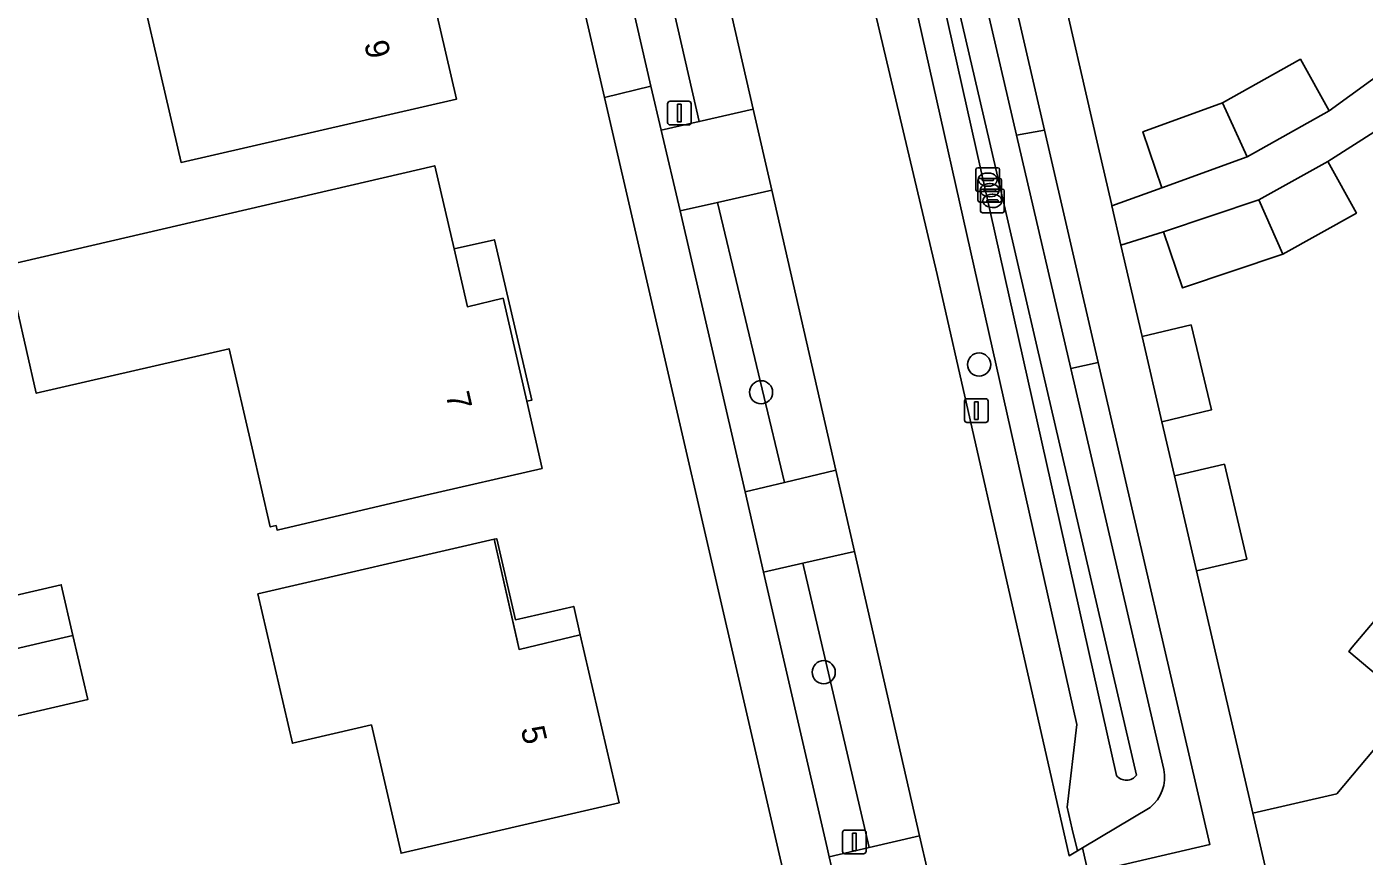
# Model space of a CAD drawing. Extents: x 156412 to 157779, y 382335 to 383768.
# Drawn here: x 156724.8 to 156781.3, y 382497.6 to 382532.6 of the extents above; entities that cross this region are included whole.
import ezdxf

# ---------------------------------------------------------------- set-up
doc = ezdxf.new("R2010")
doc.units = 0
for name, color, linetype in [('IMGEO_Berm_groen', 7, 'Continuous'), ('IMGEO_Boom', 7, 'Continuous'), ('IMGEO_Erf', 7, 'Continuous'), ('IMGEO_Greppel_droge_sloot', 7, 'Continuous'), ('IMGEO_Groenvoorziening', 7, 'Continuous'), ('IMGEO_Haag', 7, 'Continuous'), ('IMGEO_Kolk', 7, 'Continuous'), ('IMGEO_Lichtmast', 7, 'Continuous'), ('IMGEO_Muur', 7, 'Continuous'), ('IMGEO_Oever', 7, 'Continuous'), ('IMGEO_Pand', 7, 'Continuous'), ('IMGEO_Pand_nummerreeks', 7, 'Continuous'), ('IMGEO_Pand_overbouw', 7, 'Continuous'), ('IMGEO_Parkeervlak_halfverhard', 7, 'Continuous'), ('IMGEO_Rijbaan_lokaal_gesloten', 7, 'Continuous'), ('IMGEO_Rijbaan_lokaal_open', 7, 'Continuous'), ('IMGEO_Voetpad_open', 7, 'Continuous')]:
    doc.layers.add(name, color=color, linetype=linetype)

msp = doc.modelspace()

# ---------------------------------------------------------------- linework, layer by layer
at = {"layer": 'IMGEO_Berm_groen'}
for points in [[(156761.17, 382551.497), (156766.618, 382528.052), (156767.799, 382528.265), (156761.759, 382554.359), (156755.942, 382553.09), (156763.253, 382522.164), (156768.84, 382497.586), (156769.196, 382497.794), (156768.975, 382498.713), (156768.76, 382499.635), (156769.162, 382503.135), (156758.444, 382550.927)], [(156770.072, 382518.443), (156768.911, 382518.185), (156772.85, 382501.232)], [(156772.262, 382499.622), (156769.404, 382497.915), (156769.645, 382496.868), (156774.79, 382498.059), (156770.072, 382518.443)]]:
    msp.add_lwpolyline(points, dxfattribs=at)
for points in [[(156750.596, 382539.967), (156748.98, 382539.595), (156751.144, 382530.124), (156751.594, 382528.262), (156753.199, 382528.63)], [(156753.975, 382525.21), (156752.389, 382524.85), (156755.144, 382512.971), (156756.797, 382513.365)], [(156757.579, 382509.955), (156755.922, 382509.575), (156758.61, 382497.915), (156758.696, 382497.546), (156760.378, 382497.938)]]:
    msp.add_lwpolyline(points, close=True, dxfattribs=at)
msp.add_arc((156771.214, 382500.917), 1.666, 308.9884, 10.8855, dxfattribs=at)
at = {"layer": 'IMGEO_Boom'}
for centre in [(156765.034, 382518.358), (156755.813, 382517.184), (156758.461, 382505.347)]:
    msp.add_circle(centre, 0.489, dxfattribs=at)
at = {"layer": 'IMGEO_Erf'}
for points in [[(156752.438, 382451.193), (156764.119, 382465.046), (156760.304, 382481.722), (156756.624, 382497.478), (156749.185, 382529.649), (156731.446, 382606.382), (156727.839, 382622.057), (156720.348, 382620.401), (156721.249, 382616.488), (156722.772, 382616.838), (156724.915, 382607.561), (156715.64, 382605.418), (156713.892, 382612.982), (156707.186, 382611.397), (156705.872, 382617.015), (156705.651, 382617.283), (156696.258, 382615.091), (156722.867, 382500), (156729.689, 382470.495)], [(156734.136, 382540.407), (156736.368, 382540.926), (156737.306, 382536.85), (156739.393, 382537.323), (156740.204, 382537.506), (156740.776, 382535.058), (156741.624, 382535.247), (156742.933, 382529.583), (156731.282, 382526.906), (156729.618, 382534.069), (156729.416, 382534.937), (156725.893, 382534.106), (156725.018, 382537.78), (156724.904, 382538.26)], [(156742.013, 382526.766), (156742.829, 382523.243), (156743.395, 382520.802), (156744.902, 382521.157), (156745.9, 382516.805), (156746.552, 382513.962), (156741.638, 382512.837), (156735.345, 382511.36), (156735.3, 382511.551), (156735.054, 382511.494), (156734.286, 382514.824), (156733.315, 382519.028), (156725.158, 382517.143), (156723.923, 382522.561)], [(156744.52, 382510.968), (156745.581, 382506.311), (156748.168, 382506.925), (156749.808, 382499.824), (156740.589, 382497.695), (156739.336, 382503.119), (156735.991, 382502.347), (156734.532, 382508.661)], [(156727.346, 382504.197), (156723.761, 382503.366), (156723.129, 382506.072), (156721.653, 382505.729), (156721.156, 382507.872), (156726.217, 382509.046), (156726.714, 382506.903)]]:
    msp.add_lwpolyline(points, close=True, dxfattribs=at)
for points in [[(156782.269, 382547.821), (156776.998, 382546.602), (156771.884, 382545.42), (156772.162, 382544.211), (156772.024, 382544.18), (156766.55, 382542.92), (156770.067, 382527.583), (156770.629, 382525.152), (156770.648, 382525.072), (156772.758, 382525.835), (156771.958, 382528.204), (156775.328, 382529.423), (156778.62, 382531.268), (156779.843, 382529.087), (156783.336, 382531.627)], [(156782.854, 382528.897), (156779.774, 382526.948), (156780.99, 382524.764), (156777.878, 382523.03), (156773.637, 382521.596), (156772.836, 382523.964), (156771.034, 382523.398), (156771.928, 382519.54), (156773.999, 382520.034), (156774.857, 382516.441), (156772.762, 382515.941), (156773.291, 382513.654), (156775.406, 382514.141), (156776.362, 382510.131), (156774.221, 382509.638), (156776.61, 382499.385), (156780.161, 382500.209), (156783.34, 382503.976), (156780.665, 382506.23), (156780.814, 382506.406), (156784.311, 382510.531)]]:
    msp.add_lwpolyline(points, dxfattribs=at)
at = {"layer": 'IMGEO_Greppel_droge_sloot'}
for points in [[(156759.578, 382551.27), (156770.846, 382500.975)], [(156765.467, 382527.785), (156760.034, 382551.167)], [(156771.692, 382500.993), (156767.76, 382517.918), (156765.467, 382527.785)]]:
    msp.add_lwpolyline(points, dxfattribs=at)
msp.add_arc((156771.262, 382501.322), 0.542, 219.8792, 322.5585, dxfattribs=at)
at = {"layer": 'IMGEO_Groenvoorziening'}
msp.add_lwpolyline([(156767.799, 382528.265), (156766.618, 382528.052), (156768.911, 382518.185), (156770.072, 382518.443)], close=True, dxfattribs=at)
at = {"layer": 'IMGEO_Haag'}
msp.add_lwpolyline([(156767.799, 382528.265), (156766.618, 382528.052), (156768.911, 382518.185), (156770.072, 382518.443)], close=True, dxfattribs=at)
at = {"layer": 'IMGEO_Kolk'}
for p, q in [((156764.899, 382525.75), (156764.899, 382526.602)), ((156764.974, 382526.676), (156765.826, 382526.676)), ((156765.9, 382526.602), (156765.9, 382525.75)), ((156764.983, 382525.301), (156764.983, 382526.153)), ((156765.058, 382526.227), (156765.91, 382526.227)), ((156765.158, 382526.17), (156765.158, 382526.182)), ((156765.596, 382526.133), (156765.198, 382526.133)), ((156765.201, 382526.219), (156765.599, 382526.219)), ((156765.387, 382526.456), (156765.412, 382526.456)), ((156765.471, 382526.007), (156765.496, 382526.007)), ((156765.642, 382526.182), (156765.642, 382526.17)), ((156765.984, 382526.153), (156765.984, 382525.301)), ((156765.826, 382525.676), (156764.974, 382525.676)), ((156765.097, 382524.849), (156765.097, 382525.701)), ((156765.172, 382525.775), (156766.024, 382525.775)), ((156765.242, 382525.721), (156765.242, 382525.733)), ((156765.68, 382525.684), (156765.282, 382525.684)), ((156765.285, 382525.77), (156765.683, 382525.77)), ((156765.41, 382525.896), (156765.385, 382525.896)), ((156765.494, 382525.447), (156765.469, 382525.447)), ((156765.585, 382525.555), (156765.61, 382525.555)), ((156765.726, 382525.733), (156765.726, 382525.721)), ((156766.098, 382525.701), (156766.098, 382524.849)), ((156765.91, 382525.227), (156765.058, 382525.227)), ((156765.356, 382525.269), (156765.356, 382525.281)), ((156765.794, 382525.232), (156765.396, 382525.232)), ((156765.399, 382525.318), (156765.797, 382525.318)), ((156765.608, 382524.995), (156765.583, 382524.995)), ((156765.84, 382525.281), (156765.84, 382525.269)), ((156766.024, 382524.775), (156765.172, 382524.775))]:
    msp.add_line(p, q, dxfattribs=at)
for points in [[(156764.899, 382525.75), (156764.899, 382526.602)], [(156764.974, 382526.676), (156765.826, 382526.676)], [(156765.9, 382526.602), (156765.9, 382525.75)], [(156764.983, 382525.301), (156764.983, 382526.153)], [(156765.058, 382526.227), (156765.91, 382526.227)], [(156765.984, 382526.153), (156765.984, 382525.301)], [(156765.826, 382525.676), (156764.974, 382525.676)], [(156765.097, 382524.849), (156765.097, 382525.701)], [(156765.172, 382525.775), (156766.024, 382525.775)], [(156766.098, 382525.701), (156766.098, 382524.849)], [(156765.91, 382525.227), (156765.058, 382525.227)], [(156766.024, 382524.775), (156765.172, 382524.775)]]:
    msp.add_lwpolyline(points, dxfattribs=at)
for centre, radius, start, end in [((156764.976, 382526.6), 0.0765, 91.552, 178.448), ((156764.976, 382526.6), 0.0765, 91.552, 178.448), ((156765.824, 382526.6), 0.0765, 1.552, 88.448), ((156765.824, 382526.6), 0.0765, 1.552, 88.448), ((156765.06, 382526.151), 0.0765, 91.552, 178.448), ((156765.06, 382526.151), 0.0765, 91.552, 178.448), ((156765.198, 382526.179), 0.0403, 85.8775, 175.7526), ((156765.195, 382526.169), 0.0366, 178.938, 274.7102), ((156765.599, 382526.176), 0.043, 264.8664, 352.4533), ((156765.603, 382526.181), 0.0386, 1.7309, 96.639), ((156765.908, 382526.151), 0.0765, 1.552, 88.448), ((156765.908, 382526.151), 0.0765, 1.552, 88.448), ((156764.976, 382525.752), 0.0765, 181.552, 268.448), ((156764.976, 382525.752), 0.0765, 181.552, 268.448), ((156765.174, 382525.699), 0.0765, 91.552, 178.448), ((156765.174, 382525.699), 0.0765, 91.552, 178.448), ((156765.282, 382525.73), 0.0403, 85.8775, 175.7526), ((156765.279, 382525.72), 0.0366, 178.938, 274.7102), ((156765.683, 382525.727), 0.043, 264.8664, 352.4533), ((156765.687, 382525.732), 0.0386, 1.7309, 96.639), ((156765.824, 382525.752), 0.0765, 271.552, 358.448), ((156765.824, 382525.752), 0.0765, 271.552, 358.448), ((156766.022, 382525.699), 0.0765, 1.552, 88.448), ((156766.022, 382525.699), 0.0765, 1.552, 88.448), ((156765.06, 382525.303), 0.0765, 181.552, 268.448), ((156765.06, 382525.303), 0.0765, 181.552, 268.448), ((156765.174, 382524.851), 0.0765, 181.552, 268.448), ((156765.174, 382524.851), 0.0765, 181.552, 268.448), ((156765.396, 382525.278), 0.0403, 85.8775, 175.7526), ((156765.393, 382525.268), 0.0366, 178.938, 274.7102), ((156765.797, 382525.275), 0.043, 264.8664, 352.4533), ((156765.801, 382525.28), 0.0386, 1.7309, 96.639), ((156765.908, 382525.303), 0.0765, 271.552, 358.448), ((156765.908, 382525.303), 0.0765, 271.552, 358.448), ((156766.022, 382524.851), 0.0765, 271.552, 358.448), ((156766.022, 382524.851), 0.0765, 271.552, 358.448)]:
    msp.add_arc(centre, radius, start, end, dxfattribs=at)
for centre, major_axis, ratio, start_param, end_param in [((156765.386, 382526.176), (-0.387, 0.002), 0.722429, 4.712389, 7.853982), ((156765.47, 382525.727), (-0.387, 0.002), 0.722429, 4.712389, 7.853982), ((156765.411, 382526.176), (-0.39, 0.002), 0.717154, 1.570796, 4.712389), ((156765.495, 382525.727), (-0.39, 0.002), 0.717154, 1.570796, 4.712389), ((156765.584, 382525.275), (-0.387, 0.002), 0.722429, 4.712389, 7.853982), ((156765.609, 382525.275), (-0.39, 0.002), 0.717154, 1.570796, 4.712389)]:
    msp.add_ellipse(centre, major_axis=major_axis, ratio=ratio, start_param=start_param, end_param=end_param, dxfattribs=at)
at = {"layer": 'IMGEO_Lichtmast'}
for p, q in [((156751.862, 382528.588), (156751.862, 382529.388)), ((156751.862, 382529.388), (156751.862, 382528.588)), ((156751.962, 382529.488), (156752.752, 382529.488)), ((156752.752, 382529.488), (156751.962, 382529.488)), ((156752.852, 382529.388), (156752.852, 382528.588)), ((156752.852, 382528.588), (156752.852, 382529.388)), ((156752.752, 382528.488), (156751.962, 382528.488)), ((156751.962, 382528.488), (156752.752, 382528.488)), ((156764.521, 382516.912), (156765.311, 382516.912)), ((156765.311, 382516.912), (156764.521, 382516.912)), ((156764.421, 382516.012), (156764.421, 382516.812)), ((156764.421, 382516.812), (156764.421, 382516.012)), ((156765.411, 382516.812), (156765.411, 382516.012)), ((156765.411, 382516.012), (156765.411, 382516.812)), ((156765.311, 382515.912), (156764.521, 382515.912)), ((156764.521, 382515.912), (156765.311, 382515.912)), ((156759.261, 382497.771), (156759.261, 382498.571)), ((156759.261, 382498.571), (156759.261, 382497.771)), ((156759.361, 382498.671), (156760.151, 382498.671)), ((156760.151, 382498.671), (156759.361, 382498.671)), ((156760.251, 382498.571), (156760.251, 382497.771)), ((156760.251, 382497.771), (156760.251, 382498.571)), ((156760.151, 382497.671), (156759.361, 382497.671)), ((156759.361, 382497.671), (156760.151, 382497.671))]:
    msp.add_line(p, q, dxfattribs=at)
for points in [[(156752.282, 382529.363), (156752.432, 382529.363), (156752.432, 382528.613), (156752.282, 382528.613), (156752.282, 382529.363)], [(156764.841, 382516.787), (156764.991, 382516.787), (156764.991, 382516.037), (156764.841, 382516.037), (156764.841, 382516.787)], [(156759.681, 382498.546), (156759.831, 382498.546), (156759.831, 382497.796), (156759.681, 382497.796), (156759.681, 382498.546)]]:
    msp.add_lwpolyline(points, dxfattribs=at)
for centre, start, end in [((156751.962, 382529.388), 90, 180), ((156751.962, 382529.388), 90, 180), ((156752.752, 382529.388), 0, 90), ((156752.752, 382529.388), 360, 90), ((156751.962, 382528.588), 180, 270), ((156751.962, 382528.588), 180, 270), ((156752.752, 382528.588), 270, 0), ((156752.752, 382528.588), 270, 0), ((156764.521, 382516.812), 90, 180), ((156764.521, 382516.812), 90, 180), ((156765.311, 382516.812), 0, 90), ((156765.311, 382516.812), 360, 90), ((156764.521, 382516.012), 180, 270), ((156764.521, 382516.012), 180, 270), ((156765.311, 382516.012), 270, 0), ((156765.311, 382516.012), 270, 0), ((156759.361, 382498.571), 90, 180), ((156759.361, 382498.571), 90, 180), ((156760.151, 382498.571), 0, 90), ((156760.151, 382498.571), 360, 90), ((156759.361, 382497.771), 180, 270), ((156759.361, 382497.771), 180, 270), ((156760.151, 382497.771), 270, 0), ((156760.151, 382497.771), 270, 0)]:
    msp.add_arc(centre, 0.1, start, end, dxfattribs=at)
at = {"layer": 'IMGEO_Muur'}
for points in [[(156770.067, 382527.583), (156766.55, 382542.92)], [(156770.629, 382525.152), (156770.067, 382527.583)], [(156776.61, 382499.385), (156774.221, 382509.638)]]:
    msp.add_lwpolyline(points, dxfattribs=at)
at = {"layer": 'IMGEO_Oever'}
for points in [[(156772.85, 382501.232), (156768.911, 382518.185), (156766.618, 382528.052), (156761.17, 382551.497)], [(156758.444, 382550.927), (156769.162, 382503.135), (156768.76, 382499.635), (156768.975, 382498.713), (156769.196, 382497.794), (156769.404, 382497.915), (156772.262, 382499.622)], [(156770.846, 382500.975), (156759.578, 382551.27)], [(156760.034, 382551.167), (156765.467, 382527.785), (156767.76, 382517.918), (156771.692, 382500.993)]]:
    msp.add_lwpolyline(points, dxfattribs=at)
for centre, radius, start, end in [((156771.214, 382500.917), 1.666, 308.9884, 10.8855), ((156771.262, 382501.322), 0.542, 219.8792, 322.5585)]:
    msp.add_arc(centre, radius, start, end, dxfattribs=at)
at = {"layer": 'IMGEO_Pand'}
for points in [[(156734.136, 382540.407), (156724.904, 382538.26), (156725.018, 382537.78), (156725.893, 382534.106), (156729.416, 382534.937), (156729.618, 382534.069), (156731.282, 382526.906), (156742.933, 382529.583), (156741.624, 382535.247), (156740.776, 382535.058), (156740.204, 382537.506), (156739.393, 382537.323), (156737.306, 382536.85), (156736.368, 382540.926)], [(156775.328, 382529.423), (156776.371, 382527.142), (156779.843, 382529.087), (156778.62, 382531.268)], [(156775.328, 382529.423), (156771.958, 382528.204), (156772.758, 382525.835), (156776.371, 382527.142)], [(156744.902, 382521.157), (156743.395, 382520.802), (156742.829, 382523.243), (156742.013, 382526.766), (156723.923, 382522.561), (156725.158, 382517.143), (156733.315, 382519.028), (156734.286, 382514.824), (156735.054, 382511.494), (156735.3, 382511.551), (156735.345, 382511.36), (156741.638, 382512.837), (156746.552, 382513.962), (156745.9, 382516.805)], [(156776.861, 382525.326), (156777.878, 382523.03), (156780.99, 382524.764), (156779.774, 382526.948)], [(156776.861, 382525.326), (156772.836, 382523.964), (156773.637, 382521.596), (156777.878, 382523.03)], [(156771.928, 382519.54), (156772.762, 382515.941), (156774.857, 382516.441), (156773.999, 382520.034)], [(156775.406, 382514.141), (156773.291, 382513.654), (156774.221, 382509.638), (156776.362, 382510.131)], [(156744.52, 382510.968), (156734.532, 382508.661), (156735.991, 382502.347), (156739.336, 382503.119), (156740.589, 382497.695), (156749.808, 382499.824), (156748.168, 382506.925), (156745.581, 382506.311)], [(156783.34, 382503.976), (156783.485, 382504.149), (156788.454, 382499.952), (156791.934, 382504.06), (156784.311, 382510.531), (156780.814, 382506.406), (156780.665, 382506.23)], [(156726.714, 382506.903), (156726.217, 382509.046), (156721.156, 382507.872), (156721.653, 382505.729), (156723.129, 382506.072), (156725.554, 382506.634)], [(156726.714, 382506.903), (156725.554, 382506.634), (156723.129, 382506.072), (156723.761, 382503.366), (156727.346, 382504.197)], [(156783.34, 382503.976), (156780.161, 382500.209), (156776.61, 382499.385), (156777.938, 382493.666), (156779.822, 382494.101), (156781.958, 382492.284), (156788.454, 382499.952), (156783.485, 382504.149)]]:
    msp.add_lwpolyline(points, close=True, dxfattribs=at)
at = {"layer": 'IMGEO_Pand_overbouw'}
for points in [[(156745.9, 382516.805), (156746.119, 382516.857), (156744.533, 382523.635), (156742.829, 382523.243), (156743.395, 382520.802), (156744.902, 382521.157)], [(156748.16, 382506.923), (156748.168, 382506.925), (156747.889, 382508.133), (156745.424, 382507.564), (156744.631, 382510.994), (156744.52, 382510.968), (156745.479, 382506.756), (156745.581, 382506.311)]]:
    msp.add_lwpolyline(points, close=True, dxfattribs=at)
at = {"layer": 'IMGEO_Parkeervlak_halfverhard'}
for points in [[(156752.886, 382540.494), (156750.596, 382539.967), (156753.199, 382528.63), (156755.483, 382529.155)], [(156756.267, 382525.73), (156753.975, 382525.21), (156756.797, 382513.365), (156758.98, 382513.885)], [(156759.765, 382510.456), (156757.579, 382509.955), (156760.378, 382497.938), (156762.517, 382498.436)]]:
    msp.add_lwpolyline(points, close=True, dxfattribs=at)
at = {"layer": 'IMGEO_Rijbaan_lokaal_gesloten'}
for points in [[(156740.236, 382622.783), (156734.534, 382619.97), (156737.465, 382607.39), (156738.207, 382604.05), (156741.046, 382591.789), (156741.818, 382588.464), (156744.762, 382575.716), (156745.66, 382571.818), (156746.528, 382567.964), (156747.014, 382565.93), (156748.216, 382560.704), (156748.966, 382557.349), (156749.814, 382553.79), (156750.255, 382551.783), (156751.983, 382544.378), (156752.886, 382540.494), (156755.483, 382529.155), (156756.267, 382525.73), (156758.98, 382513.885), (156759.765, 382510.456), (156762.517, 382498.436), (156762.868, 382496.904)], [(156770.161, 382494.89), (156769.901, 382495.677), (156769.645, 382496.868), (156769.404, 382497.915), (156769.196, 382497.794), (156768.84, 382497.586), (156763.253, 382522.164), (156755.942, 382553.09), (156755.709, 382554.074)]]:
    msp.add_lwpolyline(points, dxfattribs=at)
at = {"layer": 'IMGEO_Rijbaan_lokaal_open'}
for points in [[(156755.483, 382529.155), (156753.199, 382528.63), (156751.594, 382528.262), (156752.389, 382524.85), (156753.975, 382525.21), (156756.267, 382525.73)], [(156758.98, 382513.885), (156756.797, 382513.365), (156755.144, 382512.971), (156755.922, 382509.575), (156757.579, 382509.955), (156759.765, 382510.456)]]:
    msp.add_lwpolyline(points, close=True, dxfattribs=at)
msp.add_lwpolyline([(156762.868, 382496.904), (156762.517, 382498.436), (156760.378, 382497.938), (156758.696, 382497.546), (156759.485, 382494.152), (156761.017, 382494.516), (156763.267, 382495.05)], dxfattribs=at)
at = {"layer": 'IMGEO_Voetpad_open'}
for points in [[(156727.839, 382622.057), (156731.446, 382606.382), (156749.185, 382529.649), (156751.144, 382530.124), (156748.98, 382539.595), (156748.095, 382543.494), (156746.361, 382550.955), (156745.901, 382552.932), (156745.089, 382556.441), (156744.346, 382559.777), (156743.096, 382565.021), (156744.585, 382565.366), (156747.014, 382565.93), (156746.528, 382567.964), (156744.356, 382567.456), (156742.634, 382567.053), (156741.736, 382570.911), (156740.839, 382574.798), (156737.902, 382587.559), (156737.117, 382590.861), (156734.29, 382603.129), (156733.515, 382606.484), (156733.428, 382606.845), (156730.627, 382619.077)], [(156776.61, 382499.385), (156774.221, 382509.638), (156773.291, 382513.654), (156772.762, 382515.941), (156771.928, 382519.54), (156771.034, 382523.398), (156770.648, 382525.072), (156770.629, 382525.152), (156770.067, 382527.583), (156766.55, 382542.92), (156763.544, 382555.909), (156762.868, 382558.825), (156762.402, 382560.842), (156760.387, 382560.376), (156760.917, 382557.986)], [(156755.709, 382554.074), (156755.942, 382553.09), (156761.759, 382554.359), (156767.799, 382528.265), (156770.072, 382518.443), (156774.79, 382498.059), (156769.645, 382496.868), (156769.901, 382495.677), (156770.161, 382494.89), (156775.246, 382496.086), (156775.911, 382493.198), (156776.101, 382492.374)], [(156783.336, 382531.627), (156779.843, 382529.087), (156776.371, 382527.142), (156772.758, 382525.835), (156770.648, 382525.072), (156771.034, 382523.398), (156772.836, 382523.964), (156776.861, 382525.326), (156779.774, 382526.948), (156782.854, 382528.897)], [(156758.696, 382497.546), (156758.61, 382497.915), (156755.922, 382509.575), (156755.144, 382512.971), (156752.389, 382524.85), (156751.594, 382528.262), (156751.144, 382530.124), (156749.185, 382529.649), (156756.624, 382497.478), (156760.304, 382481.722), (156764.119, 382465.046), (156764.67, 382462.637), (156765.051, 382460.434), (156765.589, 382459.936)], [(156777.911, 382489.441), (156778.126, 382492.845), (156777.938, 382493.666), (156776.61, 382499.385)]]:
    msp.add_lwpolyline(points, dxfattribs=at)

# ---------------------------------------------------------------- texts
at = {"layer": 'IMGEO_Pand_nummerreeks'}
for s, rotation, p in [('9', 283.0077, (156739.021, 382531.945)), ('7', 282.9143, (156742.469, 382517.091)), ('5', 283.2867, (156745.644, 382502.955))]:
    msp.add_text(s, height=1, rotation=rotation, dxfattribs=at).set_placement(p)

doc.saveas('drawing.dxf')
